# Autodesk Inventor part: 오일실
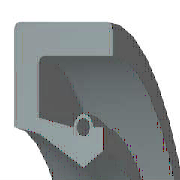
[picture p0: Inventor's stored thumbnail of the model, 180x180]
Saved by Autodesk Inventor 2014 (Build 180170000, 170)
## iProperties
IsCustomPart: 1
Company: 한국ATC센터
Created: 2014-10
Part Number: 오일실
Material: 고무
Description: 오일-실
Document SubType Name: Modeling
Standard: KS B 2804
Designer: 한국ATC센터
Standards Organization: KS
Language: ko-KR
Size Designation: S - 25 40 8
Categories: <MemberInstance><Categories><Category DisplayName="샤프트 부품" InternalName="7f7aeb1f-a693-4053-b835-cee3144e0d98" Mnemonic="SHFT"><Category DisplayName="실링" Intern
Density: 0.93 g/cm^3
Mass: 2.48215 g
Surface Area: 40.3381 cm^2
Volume: 2.66898 cm^3
Appearance: 고무 - 검은색 - 버전 1.1
Author: KYOUNG IL JANG
Revision Number: 1
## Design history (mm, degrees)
revolve "본체" stored, may be unused: angle "d17" = 90 deg
revolve "스프링1" stored, may be unused: angle "d18" = 90 deg
body "Solid1"
sketch "스케치1"
  geometry: L1 (0, 20)-(8, 20); L2 (8, 20)-(8, 18.75); L3 (8, 18.75)-(1.75, 18.75); L4 (0, 20)-(0, 14.6); L5 (0, 14.6)-(1.75, 14.25); L6 (1.75, 14.25)-(4.9, 12.5); L7 (4.9, 12.5)-(0, 12.5); L8 (6.3, 13.375)-(6.3, 14.6); L9 (0, 0)-(9.586, 0) reference; L10 (4.9, 12.5)-(6.3, 13.375); L11 (0, 18)-(0, -3) reference; L12 (-1.917, 0)-(11.503, 0) reference; L13 (4.2, 14.6)-(1.75, 15.09); L14 (1.75, 15.09)-(1.75, 18.75); L15 (6.3, 14.6)-(5.6, 14.6); C1 r 0.455 at (4.9, 14.6); A1 r 0.7 centre (4.9, 14.6) between (5.6, 14.6) and (4.2, 14.6)
  constraints: 26 end point, 5 horizontal alignment, 4 perpendicular, 2 centre point, 2 collinear, 2 horizontal, 2 parallel, 2 point on circle, 2 point on line, 2 vertical alignment, 1 coincident
  dimensions: "d0" = 40 diameter of L1 L9 (= SD2); "d1" = 26.75 diameter of L8.start L9 (= ABDM); "d2" = 1.25 distance of L1.end L2.end (computed from SD); "d3" = 0.91 diameter of C1 (= SPDI); "d4" = 1.4 diameter of A1 (= SPDA); "d5" = 25 diameter of L6.end L9 (= NND); "d6" = 28.5 diameter of L5.end L9 (= TKDM); "d7" = 29.2 diameter of L4.end L9 (= HLDM); "d8" = 4.9 distance from line of C1.centre L4 (= SPDST); "d9" = 6.3 distance between parallel lines of L8 L4 (= SDI); "d10" = 8 distance between parallel lines of L2 L4 (= SWDT); "d12" = 1.75 distance between parallel lines of L14 L4 (= SD)
fillet "모깎기1" dims "d11" = 0.3 (= RR)
other parameters: "SD2" = 40 [user parameter; used in 1 equation term], "SWDT" = 8 [user parameter; used in 1 equation term], "RR" = 0.3 [user parameter; used in 1 equation term], "SD" = 1.75 [user parameter; used in 2 equation terms], "NND" = 25 [user parameter; used in 1 equation term], "SPDA" = 1.4 [user parameter; used in 1 equation term], "SPDI" = 0.91 [user parameter; used in 1 equation term], "TKDM" = 28.5 [user parameter; used in 1 equation term], "HLDM" = 29.2 [user parameter; used in 1 equation term], "ABDM" = 26.75 [user parameter; used in 1 equation term], "SDI" = 6.3 [user parameter; used in 1 equation term], "SPDST" = 4.9 [user parameter; used in 1 equation term], "d13" = 0, "d14" = 0, "d15" = 0, "LAB" = 0.35 [user parameter]
